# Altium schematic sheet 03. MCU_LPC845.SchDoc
size A4; CheckedBy: 凌健鸿; Author: 张鹏; CompanyName: 广州周立功单片机科技有限公司; DocumentNumber: 3; SheetNumber: 3; SheetTotal: 5; PageSetup: Record=PageOptions|CenterHorizontal=True|CenterVertical=True|PrintScale=1.00|XCorrection=1.00|YCorrection=1.00|PrintKind=0|BorderSize=5000000|LeftOffset=0|BottomOffset=0|Orientation=2|PaperLength=1000|PaperWidth=1000|Scale=100|PaperSource=7|PrintQuality=600|MediaType=1|DitherType=10|PaperKind=A4|PrintScaleMode=1; DesignDate: 2019.2.20; CheckDate: 2019.2.20; SheetName: MCU_LPC845; SheetVersion: Rev.A; SheetDescription: LPC845最小系统
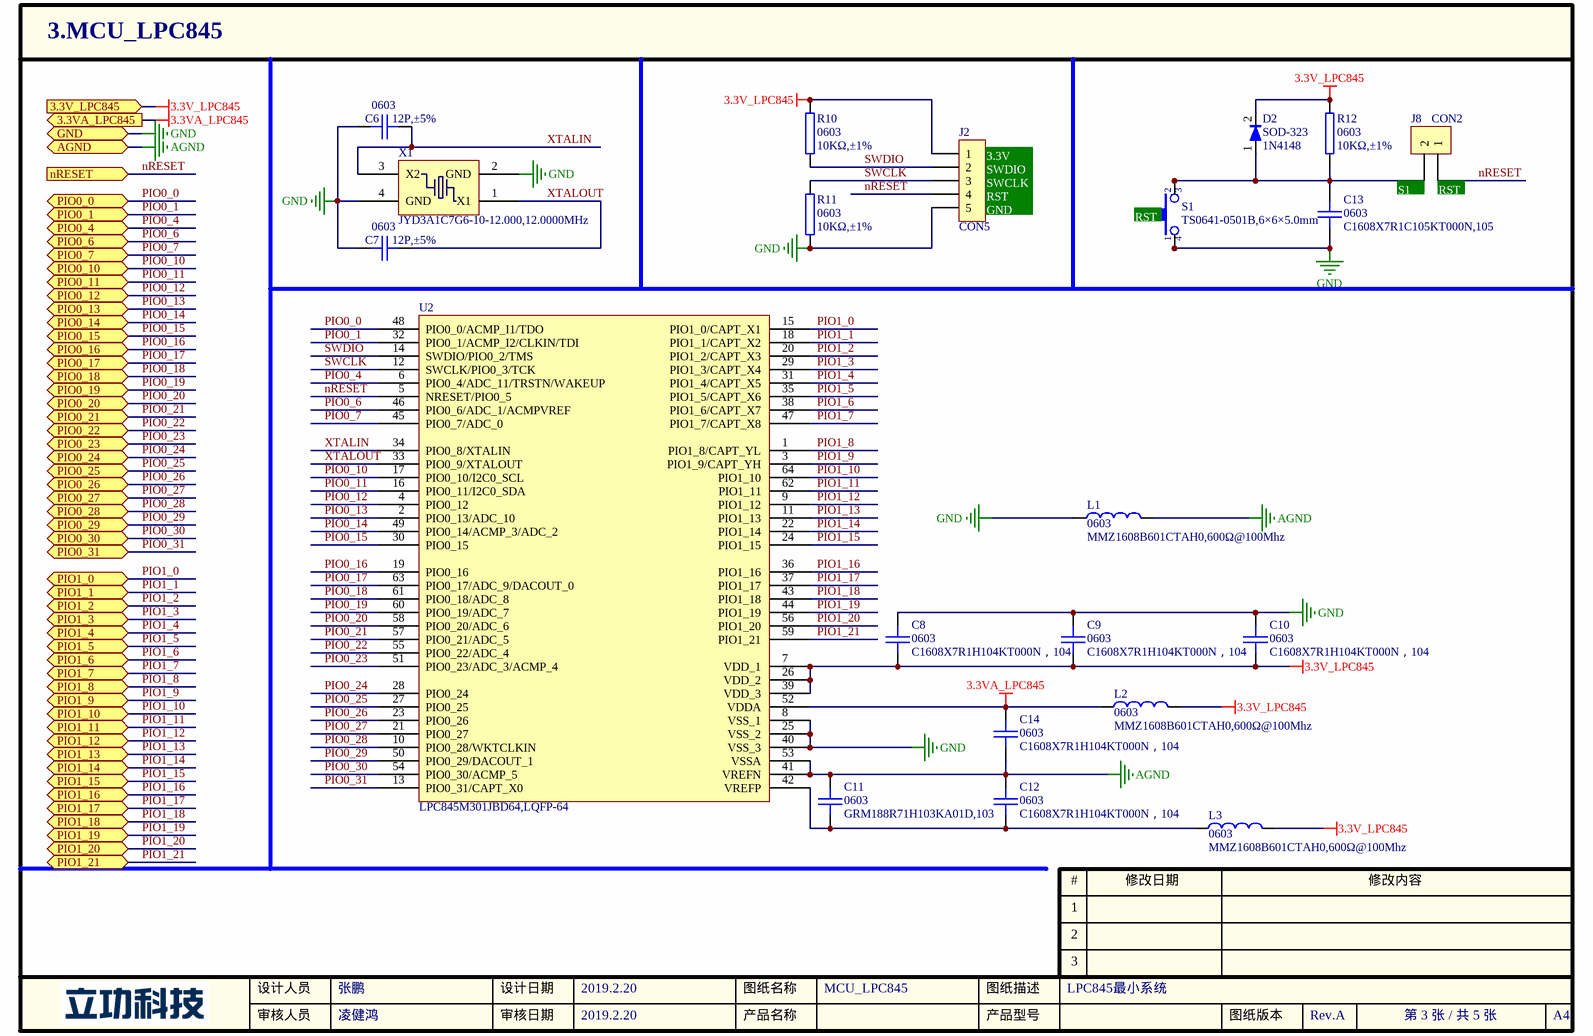
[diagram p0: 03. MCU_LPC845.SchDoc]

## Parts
C6  封装: 0603  [0603C]  (hidden comment: 12P,±5%)
C7  封装: 0603  [0603C]  (hidden comment: 12P,±5%)
C8  封装: 0603  [0603C]  (hidden comment: C1608X7R1H104KT000N，104)
C9  封装: 0603  [0603C]  (hidden comment: C1608X7R1H104KT000N，104)
C10  封装: 0603  [0603C]  (hidden comment: C1608X7R1H104KT000N，104)
C11  封装: 0603  [0603C]  (hidden comment: GRM188R71H103KA01D,103)
C12  封装: 0603  [0603C]  (hidden comment: C1608X7R1H104KT000N，104)
C13  封装: 0603  [0603C]  (hidden comment: C1608X7R1C105KT000N,105)
C14  封装: 0603  [0603C]  (hidden comment: C1608X7R1H104KT000N，104)
D2  1N4148  [SOD-323]
J2  CON5  [SIP-5-2.54-R90]
J8  CON2  [SIP-2-2.54]
L1  封装: 0603  [0603L]  (hidden comment: MMZ1608B601CTAH0,600Ω@100Mhz)
L2  封装: 0603  [0603L]  (hidden comment: MMZ1608B601CTAH0,600Ω@100Mhz)
L3  封装: 0603  [0603L]  (hidden comment: MMZ1608B601CTAH0,600Ω@100Mhz)
R10  封装: 0603  [0603R]  (hidden comment: 10KΩ,±1%)
R11  封装: 0603  [0603R]  (hidden comment: 10KΩ,±1%)
R12  封装: 0603  [0603R]  (hidden comment: 10KΩ,±1%)
S1  TS0641-0501B,6×6×5.0mm  [KEY-6S]
U2  LPC845M301JBD64,LQFP-64  [QFP50P1200X1200X160-64N]
X1  JYD3A1C7G6-10-12.000,12.0000MHz  [OSCCC250X320X80-4N]

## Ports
3.3V_LPC845 (in), 3.3VA_LPC845 (out), AGND, GND, nRESET (in), PIO0_0, PIO0_1, PIO0_4, PIO0_6, PIO0_7, PIO0_10, PIO0_11, PIO0_12, PIO0_13, PIO0_14, PIO0_15, PIO0_16, PIO0_17, PIO0_18, PIO0_19, PIO0_20, PIO0_21, PIO0_22, PIO0_23, PIO0_24, PIO0_25, PIO0_26, PIO0_27, PIO0_28, PIO0_29, PIO0_30, PIO0_31, PIO1_0, PIO1_1, PIO1_2, PIO1_3, PIO1_4, PIO1_5, PIO1_6, PIO1_7, PIO1_8, PIO1_9, PIO1_10, PIO1_11, PIO1_12, PIO1_13, PIO1_14, PIO1_15, PIO1_16, PIO1_17, PIO1_18, PIO1_19, PIO1_20, PIO1_21

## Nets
3.3V_LPC845: C8.2 C9.2 C10.2 D2.2 J2.1 L2.2 L3.2 R10.2 R12.2 U2.7(VDD_1) U2.26(VDD_2) U2.39(VDD_3) ; port 3.3V_LPC845
3.3VA_LPC845: C14.1 L2.1 U2.52(VDDA) ; port 3.3VA_LPC845
AGND: C11.1 C12.1 C14.2 L1.2 U2.41(VREFN) U2.53(VSSA) ; port AGND
GND: C6.1 C7.1 C8.1 C9.1 C10.1 C13.2 J2.5 L1.1 R11.1 S1.1 S1.4 U2.8(VSS_1) U2.25(VSS_2) U2.40(VSS_3) X1.2(GND) X1.4(GND) ; port GND
nRESET: J2.4 J8.1 U2.5(NRESET/PIO0_5) ; port nRESET
PIO0_0: U2.48(PIO0_0/ACMP_I1/TDO) ; port PIO0_0
PIO0_1: U2.32(PIO0_1/ACMP_I2/CLKIN/TDI) ; port PIO0_1
PIO0_4: U2.6(PIO0_4/ADC_11/TRSTN/WAKEUP) ; port PIO0_4
PIO0_6: U2.46(PIO0_6/ADC_1/ACMPVREF) ; port PIO0_6
PIO0_7: U2.45(PIO0_7/ADC_0) ; port PIO0_7
PIO0_10: U2.17(PIO0_10/I2C0_SCL) ; port PIO0_10
PIO0_11: U2.16(PIO0_11/I2C0_SDA) ; port PIO0_11
PIO0_12: U2.4(PIO0_12) ; port PIO0_12
PIO0_13: U2.2(PIO0_13/ADC_10) ; port PIO0_13
PIO0_14: U2.49(PIO0_14/ACMP_3/ADC_2) ; port PIO0_14
PIO0_15: U2.30(PIO0_15) ; port PIO0_15
PIO0_16: U2.19(PIO0_16) ; port PIO0_16
PIO0_17: U2.63(PIO0_17/ADC_9/DACOUT_0) ; port PIO0_17
PIO0_18: U2.61(PIO0_18/ADC_8) ; port PIO0_18
PIO0_19: U2.60(PIO0_19/ADC_7) ; port PIO0_19
PIO0_20: U2.58(PIO0_20/ADC_6) ; port PIO0_20
PIO0_21: U2.57(PIO0_21/ADC_5) ; port PIO0_21
PIO0_22: U2.55(PIO0_22/ADC_4) ; port PIO0_22
PIO0_23: U2.51(PIO0_23/ADC_3/ACMP_4) ; port PIO0_23
PIO0_24: U2.28(PIO0_24) ; port PIO0_24
PIO0_25: U2.27(PIO0_25) ; port PIO0_25
PIO0_26: U2.23(PIO0_26) ; port PIO0_26
PIO0_27: U2.21(PIO0_27) ; port PIO0_27
PIO0_28: U2.10(PIO0_28/WKTCLKIN) ; port PIO0_28
PIO0_29: U2.50(PIO0_29/DACOUT_1) ; port PIO0_29
PIO0_30: U2.54(PIO0_30/ACMP_5) ; port PIO0_30
PIO0_31: U2.13(PIO0_31/CAPT_X0) ; port PIO0_31
PIO1_0: U2.15(PIO1_0/CAPT_X1) ; port PIO1_0
PIO1_1: U2.18(PIO1_1/CAPT_X2) ; port PIO1_1
PIO1_2: U2.20(PIO1_2/CAPT_X3) ; port PIO1_2
PIO1_3: U2.29(PIO1_3/CAPT_X4) ; port PIO1_3
PIO1_4: U2.31(PIO1_4/CAPT_X5) ; port PIO1_4
PIO1_5: U2.35(PIO1_5/CAPT_X6) ; port PIO1_5
PIO1_6: U2.38(PIO1_6/CAPT_X7) ; port PIO1_6
PIO1_7: U2.47(PIO1_7/CAPT_X8) ; port PIO1_7
PIO1_8: U2.1(PIO1_8/CAPT_YL) ; port PIO1_8
PIO1_9: U2.3(PIO1_9/CAPT_YH) ; port PIO1_9
PIO1_10: U2.64(PIO1_10) ; port PIO1_10
PIO1_11: U2.62(PIO1_11) ; port PIO1_11
PIO1_12: U2.9(PIO1_12) ; port PIO1_12
PIO1_13: U2.11(PIO1_13) ; port PIO1_13
PIO1_14: U2.22(PIO1_14) ; port PIO1_14
PIO1_15: U2.24(PIO1_15) ; port PIO1_15
PIO1_16: U2.36(PIO1_16) ; port PIO1_16
PIO1_17: U2.37(PIO1_17) ; port PIO1_17
PIO1_18: U2.43(PIO1_18) ; port PIO1_18
PIO1_19: U2.44(PIO1_19) ; port PIO1_19
PIO1_20: U2.56(PIO1_20) ; port PIO1_20
PIO1_21: U2.59(PIO1_21) ; port PIO1_21
SWCLK: J2.3 R11.2 U2.12(SWCLK/PIO0_3/TCK)
SWDIO: J2.2 R10.1 U2.14(SWDIO/PIO0_2/TMS)
XTALIN: C6.2 U2.34(PIO0_8/XTALIN) X1.3(X2)
XTALOUT: C7.2 U2.33(PIO0_9/XTALOUT) X1.1(X1)
NetC11_2: C11.2 C12.2 L3.1 U2.42(VREFP)
NetC13_1: C13.1 D2.1 J8.2 R12.1 S1.2 S1.3

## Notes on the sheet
- (near J2) 3.3V
- (near J2) SWDIO
- (near J2) SWCLK
- (near J2) RST
- (near J2) GND
- (near S1) RST
- (near J8) S1
- (near J8) RST

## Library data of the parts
C6 C7 = 1.02.01.0037: GRM1885C1H120JA01D,12P,±5%,50V,COG,0603,RoHS; 名称: 电容; 设备封装名称: C0603_12P_COG_50V_5%; 厂商: muRata; 贴片和直插: SMT; 器件优选方案: 正常状态，可以选用
C8-C10 C12 C14 = 1.02.01.0072: C1608X7R1H104KT000N，104，±10%，50V，X7R,TDK,0603,RoHS; 名称: 电容; 贴片和直插: SMT; PCB备注: 151110lmd; 器件优选方案: 正常状态，可以选用
C11 = 1.02.01.0024: GRM188R71H103KA01D,103,±10%,50V,X7R,0603,muRata,RoHS; 名称: 电容; 设备封装名称: C0603_103_X7R_50V_10%; 贴片和直插: SMT; 器件优选方案: 正常状态，可以选用
C13 = 1.02.01.0036: C1608X7R1C105KT000N,105,1μF,±10%,16V,X7R,0603,TDK,RoHS; 名称: 电容; 设备封装名称: C0603_105_X7R_16V_10%; 贴片和直插: SMT; 器件优选方案: 正常状态，可以选用
D2 = 1.04.07.0027: 1N4148,SOD-323,长电,RoHS; 名称: 二极管; 设备封装名称: SOD-323_1N4148; 贴片和直插: SMT; 器件优选方案: 正常状态，可以选用
J2 = CON5: Connector
J8 = CON2: Connector
L1-L3 = 1.03.03.0026: MMZ1608B601CTAH0,600Ω@100Mhz,500mA,0603,TDK,RoHS; 名称: 磁珠; 贴片和直插: SMT; PCB备注: 160408lmd; 器件优选方案: 正常状态，可以选用
R10-R12 = 1.01.01.0052: 10KΩ,±1%,0603,*,RoHS; 名称: 电阻; 设备封装名称: R0603_10K_1%; 厂商: Ralec; 贴片和直插: SMT; 器件优选方案: 正常状态，可以选用
S1 = 1.09.01.0003: TS0641-0501B,6×6×5.0mm,黑色,SMD,卷带装,RoHS; 名称: 轻触开关; 贴片和直插: SMT; 器件优选方案: 正常状态，可以选用
U2 = 08.01.04039: LPC845M301JBD64,LQFP-64,NXP; 名称: 集成电路; 贴片和直插: SMT; PCB备注: 190321lmd
X1 = 1.07.01.0032: JYD3A1C7G6-10-12.000,12.0000MHz,±10ppm,10pF,-40~85℃,±10ppm,SMD3225,*,JYEG,RoHS; 名称: 晶体; 贴片和直插: SMT; PCB备注: 151229lmd171128ZW; 器件优选方案: 正常状态，可以选用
